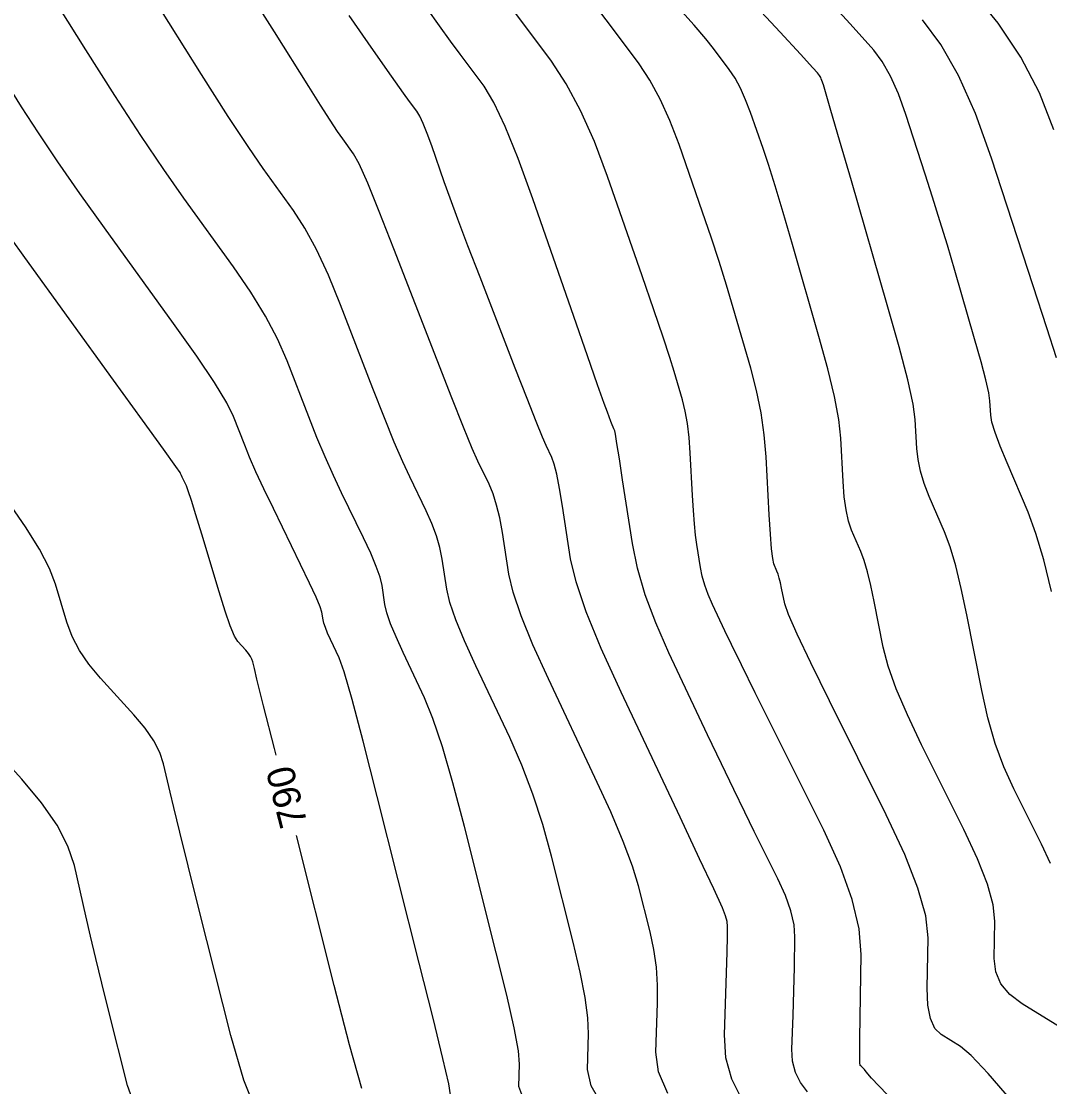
# Model space of a CAD drawing. Extents: x 2082232 to 2083549, y 592624 to 593832.
# Drawn here: x 2082485.39 to 2082511.4, y 593211.7 to 593238.65 of the extents above; entities that cross this region are included whole.
import ezdxf

# ---------------------------------------------------------------- set-up
doc = ezdxf.new("R2010")
doc.units = 0
doc.layers.add('DT_X_Contour_Major', color=7, linetype='Continuous')
doc.layers.add('DT_X_Contour_Minor', color=7, linetype='Continuous')

msp = doc.modelspace()

# ---------------------------------------------------------------- linework, layer by layer
at = {"layer": 'DT_X_Contour_Major'}
for points in [[(2082511.421, 593217.344), (2082511.192, 593217.834), (2082510.492, 593219.238), (2082510.245, 593219.788), (2082510.028, 593220.386), (2082509.842, 593221.031), (2082509.685, 593221.723), (2082509.308, 593223.634), (2082509.167, 593224.302), (2082509.025, 593224.875), (2082508.882, 593225.353), (2082508.74, 593225.736), (2082508.358, 593226.629), (2082508.231, 593226.957), (2082508.137, 593227.269), (2082508.074, 593227.566), (2082508.043, 593227.848), (2082508.004, 593228.579), (2082507.949, 593228.966), (2082507.812, 593229.579), (2082507.594, 593230.416), (2082507.294, 593231.479), (2082506.387, 593234.615), (2082506.088, 593235.648), (2082505.87, 593236.398), (2082505.733, 593236.864), (2082505.678, 593237.047), (2082505.641, 593237.155), (2082505.626, 593237.193), (2082505.611, 593237.228), (2082505.594, 593237.258), (2082505.577, 593237.284), (2082505.53, 593237.347), (2082505.413, 593237.477), (2082505.097, 593237.82), (2082504.582, 593238.374), (2082503.869, 593239.142)], [(2082503.619, 593211.386), (2082503.36, 593211.894), (2082503.213, 593212.435), (2082503.177, 593213.009), (2082503.231, 593214.584), (2082503.247, 593215.107), (2082503.255, 593215.497), (2082503.253, 593215.754), (2082503.243, 593215.877), (2082503.206, 593216.027), (2082503.123, 593216.225), (2082502.904, 593216.705), (2082502.548, 593217.469), (2082502.055, 593218.515), (2082500.56, 593221.681), (2082500.06, 593222.783), (2082499.68, 593223.712), (2082499.422, 593224.47), (2082499.284, 593225.055), (2082499.079, 593226.386), (2082499.004, 593226.837), (2082498.935, 593227.192), (2082498.871, 593227.452), (2082498.812, 593227.615), (2082498.662, 593227.923), (2082498.571, 593228.132), (2082498.41, 593228.527), (2082498.181, 593229.11), (2082497.882, 593229.878), (2082496.994, 593232.178), (2082496.687, 593232.975), (2082496.434, 593233.643), (2082496.234, 593234.18), (2082496.088, 593234.588), (2082495.77, 593235.503), (2082495.656, 593235.815), (2082495.556, 593236.064), (2082495.467, 593236.251), (2082495.392, 593236.376), (2082495.207, 593236.625), (2082495.059, 593236.831), (2082494.756, 593237.261), (2082494.298, 593237.916), (2082493.683, 593238.796)], [(2082491.832, 593220.089), (2082491.79, 593220.255), (2082491.518, 593221.336), (2082491.349, 593222.01), (2082491.283, 593222.277), (2082491.244, 593222.448), (2082491.222, 593222.514), (2082491.185, 593222.585), (2082491.133, 593222.66), (2082491.066, 593222.74), (2082490.867, 593222.959), (2082490.781, 593223.099), (2082490.673, 593223.356), (2082490.543, 593223.729), (2082490.39, 593224.219), (2082489.953, 593225.68), (2082489.806, 593226.167), (2082489.693, 593226.533), (2082489.612, 593226.777), (2082489.565, 593226.9), (2082489.484, 593227.066), (2082489.457, 593227.122), (2082489.437, 593227.164), (2082489.423, 593227.193), (2082489.416, 593227.209), (2082489.407, 593227.234), (2082489.299, 593227.388), (2082488.981, 593227.829), (2082488.455, 593228.558), (2082487.72, 593229.576), (2082485.48, 593232.673), (2082484.743, 593233.692)], [(2082494.003, 593211.655), (2082493.692, 593212.762), (2082493.303, 593214.258), (2082492.346, 593218.053)]]:
    msp.add_lwpolyline(points, dxfattribs=at)
at = {"layer": 'DT_X_Contour_Minor'}
for points in [[(2082500.125, 593211.163), (2082499.806, 593211.725), (2082499.708, 593212.138), (2082499.739, 593213.041), (2082499.723, 593213.439), (2082499.653, 593213.958), (2082499.529, 593214.595), (2082499.35, 593215.353), (2082498.799, 593217.533), (2082498.579, 593218.334), (2082498.329, 593219.1), (2082498.051, 593219.833), (2082497.743, 593220.531), (2082496.885, 593222.347), (2082496.598, 593222.979), (2082496.381, 593223.513), (2082496.232, 593223.947), (2082496.154, 593224.283), (2082496.036, 593225.046), (2082495.977, 593225.337), (2082495.891, 593225.637), (2082495.776, 593225.946), (2082495.633, 593226.264), (2082495.213, 593227.124), (2082495.037, 593227.505), (2082494.824, 593228.005), (2082494.572, 593228.624), (2082494.284, 593229.36), (2082493.463, 593231.483), (2082493.158, 593232.229), (2082492.858, 593232.875), (2082492.564, 593233.421), (2082492.274, 593233.868), (2082491.509, 593234.926), (2082491.144, 593235.455), (2082490.624, 593236.247), (2082489.949, 593237.303), (2082489.118, 593238.621), (2082486.696, 593242.49)], [(2082498.103, 593211.369), (2082497.973, 593211.702), (2082497.993, 593212.269), (2082497.962, 593212.605), (2082497.853, 593213.188), (2082497.667, 593214.016), (2082497.403, 593215.091), (2082496.596, 593218.286), (2082496.307, 593219.388), (2082496.042, 593220.298), (2082495.802, 593221.015), (2082495.587, 593221.539), (2082495.048, 593222.681), (2082494.868, 593223.078), (2082494.731, 593223.413), (2082494.638, 593223.686), (2082494.588, 593223.897), (2082494.514, 593224.376), (2082494.464, 593224.587), (2082494.369, 593224.859), (2082494.228, 593225.193), (2082494.043, 593225.588), (2082493.489, 593226.724), (2082493.282, 593227.163), (2082493.074, 593227.63), (2082492.868, 593228.123), (2082492.661, 593228.643), (2082492.111, 593230.066), (2082491.872, 593230.615), (2082491.566, 593231.193), (2082491.194, 593231.8), (2082490.756, 593232.437), (2082489.499, 593234.175), (2082488.991, 593234.899), (2082488.408, 593235.766), (2082487.751, 593236.777), (2082487.02, 593237.932), (2082484.972, 593241.204)], [(2082511.504, 593235.909), (2082511.142, 593236.84), (2082510.674, 593237.74), (2082510.098, 593238.608), (2082509.416, 593239.447)], [(2082501.742, 593211.529), (2082501.509, 593212.08), (2082501.442, 593212.574), (2082501.485, 593213.812), (2082501.485, 593214.273), (2082501.454, 593214.727), (2082501.391, 593215.175), (2082501.297, 593215.615), (2082501.002, 593216.78), (2082500.851, 593217.279), (2082500.616, 593217.903), (2082500.299, 593218.651), (2082499.899, 593219.523), (2082498.723, 593222.014), (2082498.329, 593222.881), (2082498.03, 593223.612), (2082497.827, 593224.208), (2082497.719, 593224.669), (2082497.557, 593225.716), (2082497.491, 593226.087), (2082497.413, 593226.415), (2082497.323, 593226.699), (2082497.222, 593226.939), (2082496.937, 593227.523), (2082496.793, 593227.847), (2082496.573, 593228.381), (2082496.277, 593229.124), (2082495.906, 593230.077), (2082494.815, 593232.899), (2082494.445, 593233.842), (2082494.151, 593234.557), (2082493.933, 593235.042), (2082493.792, 593235.299), (2082493.518, 593235.678), (2082493.388, 593235.867), (2082493.201, 593236.15), (2082492.96, 593236.528), (2082492.662, 593237), (2082491.795, 593238.385), (2082491.439, 593238.943)], [(2082505.275, 593211.569), (2082505.096, 593211.803), (2082504.971, 593212.061), (2082504.9, 593212.344), (2082504.884, 593212.65), (2082504.913, 593213.5), (2082504.924, 593213.816), (2082504.932, 593214.123), (2082504.94, 593214.424), (2082504.945, 593214.717), (2082504.959, 593215.489), (2082504.935, 593215.798), (2082504.855, 593216.147), (2082504.717, 593216.535), (2082504.523, 593216.962), (2082503.928, 593218.156), (2082503.687, 593218.644), (2082503.41, 593219.215), (2082503.098, 593219.868), (2082502.749, 593220.604), (2082501.77, 593222.676), (2082501.438, 593223.431), (2082501.173, 593224.144), (2082500.977, 593224.814), (2082500.849, 593225.441), (2082500.6, 593227.056), (2082500.517, 593227.587), (2082500.457, 593227.97), (2082500.418, 593228.205), (2082500.401, 593228.291), (2082500.386, 593228.323), (2082500.376, 593228.344), (2082500.36, 593228.385), (2082500.336, 593228.446), (2082500.305, 593228.526), (2082500.213, 593228.764), (2082500.134, 593228.982), (2082499.966, 593229.457), (2082499.71, 593230.19), (2082499.365, 593231.18), (2082498.326, 593234.162), (2082497.957, 593235.178), (2082497.629, 593235.992), (2082497.341, 593236.601), (2082497.094, 593237.008), (2082496.491, 593237.82), (2082496.248, 593238.152), (2082495.97, 593238.537), (2082495.659, 593238.976)], [(2082507.523, 593211.269), (2082507.078, 593211.723), (2082506.896, 593211.916), (2082506.761, 593212.08), (2082506.716, 593212.135), (2082506.68, 593212.176), (2082506.654, 593212.204), (2082506.638, 593212.217), (2082506.608, 593212.235), (2082506.6, 593212.316), (2082506.597, 593212.545), (2082506.599, 593212.923), (2082506.607, 593213.448), (2082506.635, 593215.047), (2082506.584, 593215.693), (2082506.408, 593216.432), (2082506.109, 593217.265), (2082505.687, 593218.191), (2082504.394, 593220.784), (2082503.955, 593221.667), (2082503.608, 593222.369), (2082503.352, 593222.89), (2082503.188, 593223.232), (2082502.872, 593223.901), (2082502.764, 593224.148), (2082502.677, 593224.386), (2082502.612, 593224.615), (2082502.568, 593224.836), (2082502.479, 593225.414), (2082502.447, 593225.654), (2082502.418, 593225.941), (2082502.391, 593226.275), (2082502.368, 593226.655), (2082502.311, 593227.733), (2082502.282, 593228.12), (2082502.24, 593228.473), (2082502.183, 593228.792), (2082502.113, 593229.077), (2082501.906, 593229.791), (2082501.797, 593230.143), (2082501.626, 593230.663), (2082501.392, 593231.353), (2082501.095, 593232.211), (2082500.22, 593234.723), (2082499.885, 593235.612), (2082499.536, 593236.395), (2082499.173, 593237.07), (2082498.797, 593237.639), (2082497.775, 593239.015)], [(2082510.437, 593211.352), (2082509.843, 593212.036), (2082509.413, 593212.491), (2082509.147, 593212.718), (2082508.656, 593213.017), (2082508.496, 593213.175), (2082508.384, 593213.424), (2082508.32, 593213.765), (2082508.304, 593214.197), (2082508.326, 593215.469), (2082508.266, 593216.022), (2082508.07, 593216.725), (2082507.737, 593217.578), (2082507.268, 593218.582), (2082505.834, 593221.459), (2082505.36, 593222.421), (2082505.013, 593223.151), (2082504.793, 593223.649), (2082504.7, 593223.913), (2082504.622, 593224.309), (2082504.593, 593224.448), (2082504.563, 593224.566), (2082504.534, 593224.665), (2082504.504, 593224.745), (2082504.425, 593224.93), (2082504.396, 593225.059), (2082504.366, 593225.309), (2082504.337, 593225.679), (2082504.307, 593226.169), (2082504.229, 593227.637), (2082504.182, 593228.189), (2082504.102, 593228.747), (2082503.988, 593229.31), (2082503.84, 593229.878), (2082503.4, 593231.399), (2082503.227, 593231.978), (2082503.04, 593232.575), (2082502.839, 593233.19), (2082502.623, 593233.823), (2082502.027, 593235.534), (2082501.796, 593236.143), (2082501.551, 593236.685), (2082501.292, 593237.162), (2082501.019, 593237.573), (2082500.27, 593238.58), (2082499.993, 593238.944)], [(2082511.655, 593213.218), (2082510.703, 593213.799), (2082510.391, 593214.034), (2082510.17, 593214.303), (2082510.04, 593214.607), (2082510.001, 593214.945), (2082510.017, 593215.892), (2082509.973, 593216.303), (2082509.827, 593216.826), (2082509.579, 593217.461), (2082509.23, 593218.208), (2082508.163, 593220.348), (2082507.803, 593221.105), (2082507.521, 593221.768), (2082507.317, 593222.34), (2082507.193, 593222.818), (2082506.965, 593223.971), (2082506.88, 593224.375), (2082506.794, 593224.721), (2082506.708, 593225.009), (2082506.622, 593225.24), (2082506.392, 593225.779), (2082506.314, 593226.008), (2082506.251, 593226.289), (2082506.205, 593226.622), (2082506.175, 593227.008), (2082506.116, 593228.108), (2082506.065, 593228.578), (2082505.957, 593229.163), (2082505.791, 593229.863), (2082505.567, 593230.679), (2082504.893, 593233.007), (2082504.658, 593233.813), (2082504.455, 593234.487), (2082504.286, 593235.027), (2082504.151, 593235.435), (2082503.834, 593236.344), (2082503.711, 593236.668), (2082503.581, 593236.956), (2082503.443, 593237.21), (2082503.298, 593237.428), (2082502.9, 593237.964), (2082502.703, 593238.211), (2082502.41, 593238.551), (2082502.021, 593238.984)], [(2082511.453, 593224.229), (2082511.255, 593225.03), (2082511.056, 593225.697), (2082510.857, 593226.232), (2082510.325, 593227.479), (2082510.149, 593227.905), (2082510.022, 593228.249), (2082509.942, 593228.509), (2082509.911, 593228.687), (2082509.892, 593229.051), (2082509.862, 593229.251), (2082509.787, 593229.58), (2082509.667, 593230.036), (2082509.502, 593230.621), (2082509.001, 593232.351), (2082508.814, 593232.989), (2082508.627, 593233.607), (2082508.441, 593234.205), (2082508.257, 593234.781), (2082507.764, 593236.293), (2082507.575, 593236.82), (2082507.376, 593237.267), (2082507.168, 593237.635), (2082506.951, 593237.923), (2082506.358, 593238.586), (2082506.073, 593238.9)], [(2082511.578, 593230.135), (2082511.328, 593230.899), (2082510.982, 593231.962), (2082509.93, 593235.191), (2082509.525, 593236.318), (2082509.099, 593237.276), (2082508.652, 593238.065), (2082508.183, 593238.685)], [(2082496.247, 593211.498), (2082496.2, 593211.771), (2082496.052, 593212.418), (2082495.804, 593213.437), (2082495.456, 593214.829), (2082494.393, 593219.04), (2082494.034, 593220.443), (2082493.754, 593221.495), (2082493.553, 593222.197), (2082493.431, 593222.547), (2082493.211, 593223.014), (2082493.137, 593223.176), (2082493.081, 593223.313), (2082493.043, 593223.424), (2082493.023, 593223.511), (2082492.993, 593223.707), (2082492.95, 593223.837), (2082492.847, 593224.082), (2082492.681, 593224.44), (2082492.454, 593224.913), (2082491.765, 593226.324), (2082491.526, 593226.822), (2082491.325, 593227.254), (2082491.163, 593227.623), (2082491.039, 593227.926), (2082490.759, 593228.65), (2082490.585, 593229.001), (2082490.274, 593229.511), (2082489.825, 593230.179), (2082489.238, 593231.007), (2082487.489, 593233.424), (2082486.867, 593234.295), (2082486.311, 593235.096), (2082485.821, 593235.826), (2082485.397, 593236.486), (2082484.355, 593238.15)], [(2082491.398, 593210.909), (2082491.019, 593211.87), (2082490.69, 593212.992), (2082489.881, 593216.2), (2082489.607, 593217.287), (2082489.395, 593218.14), (2082489.243, 593218.761), (2082489.151, 593219.148), (2082488.988, 593219.871), (2082488.895, 593220.152), (2082488.738, 593220.451), (2082488.518, 593220.77), (2082488.233, 593221.109), (2082487.39, 593222.036), (2082487.1, 593222.386), (2082486.862, 593222.738), (2082486.676, 593223.093), (2082486.542, 593223.452), (2082486.255, 593224.412), (2082486.099, 593224.813), (2082485.844, 593225.296), (2082485.492, 593225.862), (2082485.043, 593226.51)], [(2082488.346, 593210.979), (2082488.077, 593211.727), (2082487.596, 593213.633), (2082487.425, 593214.318), (2082487.271, 593214.944), (2082487.136, 593215.511), (2082487.019, 593216.019), (2082486.732, 593217.294), (2082486.568, 593217.789), (2082486.291, 593218.318), (2082485.902, 593218.881), (2082485.4, 593219.477), (2082483.912, 593221.114)]]:
    msp.add_lwpolyline(points, dxfattribs=at)

# ---------------------------------------------------------------- texts
at = {"layer": 'DT_X_Contour_Major'}
msp.add_text('790', height=0.7, rotation=104.1598, dxfattribs=at).set_placement((2082492.63, 593218.355))

doc.saveas('drawing.dxf')
